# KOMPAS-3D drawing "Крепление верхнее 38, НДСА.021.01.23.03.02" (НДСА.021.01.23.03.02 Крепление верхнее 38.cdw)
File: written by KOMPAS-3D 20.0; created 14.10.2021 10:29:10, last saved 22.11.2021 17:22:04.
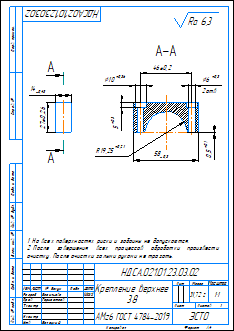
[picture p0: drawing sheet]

Sheet 1: A4, portrait

Document properties: Полное имя файла: C:\Users\s.pischagina\Desktop\PLM\НДСА.021.01.23.03.02 Крепление верхнее 38.cdw; Автор: adminzsc; Параметр неуказанной шероховатости: Ra 6,3; PLM_CDWXDTO: <item xmlns="http://appius.ru/pdm" xmlns:xs="http://www.w3.org/2001/XMLSchema" xmlns:xsi="http://www.w3.org/2001/XMLSchema-instance" xsi:type="item">  <element xmlns:d2p1="http://v8.1c.ru/8.1/data/enterprise/current-config" xsi:type="d2p1:CatalogRef.aps_Элемен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; Масса: 0.0317194; PDM_DOCXDTO: <item xmlns="http://appius.ru/pdm" xmlns:xs="http://www.w3.org/2001/XMLSchema" xmlns:xsi="http://www.w3.org/2001/XMLSchema-instance" xsi:type="item">  <element xmlns:d2p1="http://v8.1c.ru/8.1/data/enterprise/current-config" xsi:type="d2p1:CatalogRef.aps_Элемен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; PDM_ITEMXDTO: <item xmlns="http://appius.ru/pdm" xmlns:xs="http://www.w3.org/2001/XMLSchema" xmlns:xsi="http://www.w3.org/2001/XMLSchema-instance" xsi:type="item">  <element xmlns:d2p1="http://v8.1c.ru/8.1/data/enterprise/current-config" xsi:type="d2p1:CatalogRef.aps_Элемен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; PDM_DRAWINGXDTO: <item xmlns="http://appius.ru/pdm" xmlns:xs="http://www.w3.org/2001/XMLSchema" xmlns:xsi="http://www.w3.org/2001/XMLSchema-instance" xsi:type="item">  <element xmlns:d2p1="http://v8.1c.ru/8.1/data/enterprise/current-config" xsi:type="d2p1:CatalogRef.aps_Элемен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

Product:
- Part/product: Крепление верхнее 38  | designation НДСА.021.01.23.03.02
    Материал: АМг6  ГОСТ 4784-2019 (density 2640 kg/m3)
    Масса: 0.0317194
    additional columns: <item xmlns="http://appius.ru/pdm" xmlns:xs="http://www.w3.org/2001/XMLSchema" x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; <item xmlns="http://appius.ru/pdm" xmlns:xs="http://www.w3.org/2001/XMLSchema" x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; <item xmlns="http://appius.ru/pdm" xmlns:xs="http://www.w3.org/2001/XMLSchema" x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
    source file: НДСА.021.01.23.03.02 Крепление верхнее 38.cdw

Title block, sheet 1: Наименование: Крепление верхнее / 38; designation: НДСА.021.01.23.03.02; Материал: АМг6 ГОСТ 4784-2019; Масса: 31,72 г; Количество листов документа: 1; organisation: ЭСТО; Форматы листов документа: A4; stored path: C:\Users\vasilyeva\Desktop\PM_APPIUS\НДСА.002.01.06.02.00 Крепление верхнее 38.cdw; Разработал: Васильева; Проверил: Горностаев; Утвердил: Белецкий; Разработал, date: 14.10.2021

Views: Вид 1, Спереди, Разрез А-А
Referenced files in C:\Users\vasilyeva\Desktop\PM_APPIUS\: НДСА.002.01.06.02.00 Крепление верхнее 38.m3d, НДСА.021.01.23.03.02 Крепление верхнее 38.m3d
Referenced files in C:\Users\s.pischagina\Desktop\PLM\: НДСА.021.01.23.03.02 Крепление верхнее 38.m3d
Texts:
  Ra 6,3
  НДСА.021.01.23.03.02 Крепление верхнее 38
Dimensions and other numbers on the sheet: 27±0,26; 14; 58; 46±0,2; 19,25; 0,5; 10; 5; 6; 2отв; 1; 1:1; 38; 31,72 г; 14.10.2021

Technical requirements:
  На всех поверхностях риски и забоины не допускаются.
  После завершения всех процессов обработки произвести
  очистку. После очистки голыми руками не трогать.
